// Mitsubishi GX Works2 project: L02_EIP_LIBRARY   PLC: FX3G

// task Task_01 (event TRUE, interval 0, priority 31): POU_01
// user libraries (not included): BIT_TO_INT

PROGRAM POU_01
VAR
  FB_EIP_MASTER_1 : FB_EIP_MASTER;
END_VAR
(* structured ladder/FBD written out as ST: instructions are called as NAME(EN, inputs, outputs); _pN, _eN, _tN stand for wires *)
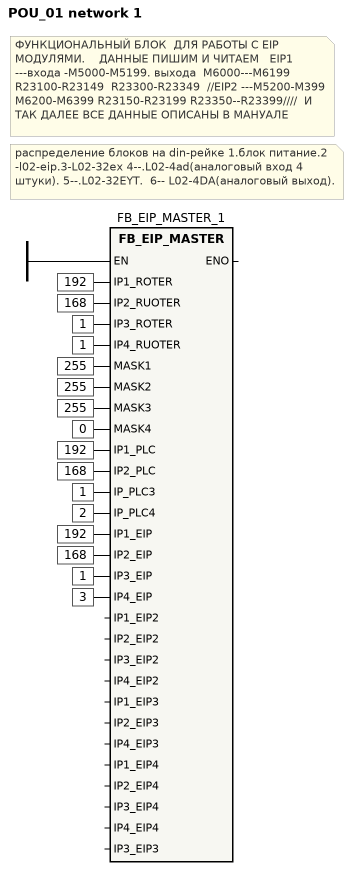
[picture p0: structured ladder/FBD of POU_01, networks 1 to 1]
(* network 1 *)
(* ФУНКЦИОНАЛЬНЫЙ БЛОК  ДЛЯ РАБОТЫ С EIP МОДУЛЯМИ.    ДАННЫЕ ПИШИМ И ЧИТАЕМ   EIP1 ---входа -М5000-М5199. выхода  M6000---M6199  R23100-R23149  R23300-R23349  //EIP2 ---M5200-M399  M6200-M6399 R23150-R23199 R23350--R23399////  И ТАК ДАЛЕЕ ВСЕ ДАННЫЕ ОПИСАНЫ В МАНУАЛЕ *)
(* распределение блоков на din-рейке 1.блок питание.2 -l02-eip.3-L02-32ex 4--.L02-4ad(аналоговый вход 4 штуки). 5--.L02-32EYT.  6-- L02-4DA(аналоговый выход). *)
FB_EIP_MASTER_1(EN := TRUE, IP1_ROTER := 192, IP2_RUOTER := 168, IP3_ROTER := 1, IP4_RUOTER := 1, MASK1 := 255, MASK2 := 255, MASK3 := 255, MASK4 := 0, IP1_PLC := 192, IP2_PLC := 168, IP_PLC3 := 1, IP_PLC4 := 2, IP1_EIP := 192, IP2_EIP := 168, IP3_EIP := 1, IP4_EIP := 3);
END_PROGRAM

FUNCTION_BLOCK FB_EIP_MASTER
VAR_INPUT
  IP1_ROTER : INT;
  IP2_RUOTER : INT;
  IP3_ROTER : INT;
  IP4_RUOTER : INT;
  MASK1 : INT;
  MASK2 : INT;
  MASK3 : INT;
  MASK4 : INT;
  IP1_PLC : INT;
  IP2_PLC : INT;
  IP_PLC3 : INT;
  IP_PLC4 : INT;
  IP1_EIP : INT;
  IP2_EIP : INT;
  IP3_EIP : INT;
  IP4_EIP : INT;
  IP1_EIP2 : INT;
  IP2_EIP2 : INT;
  IP3_EIP2 : INT;
  IP4_EIP2 : INT;
  IP1_EIP3 : INT;
  IP2_EIP3 : INT;
  IP4_EIP3 : INT;
  IP1_EIP4 : INT;
  IP2_EIP4 : INT;
  IP3_EIP4 : INT;
  IP4_EIP4 : INT;
  IP3_EIP3 : INT;
END_VAR
(* structured ladder/FBD written out as ST: instructions are called as NAME(EN, inputs, outputs); _pN, _eN, _tN stand for wires *)
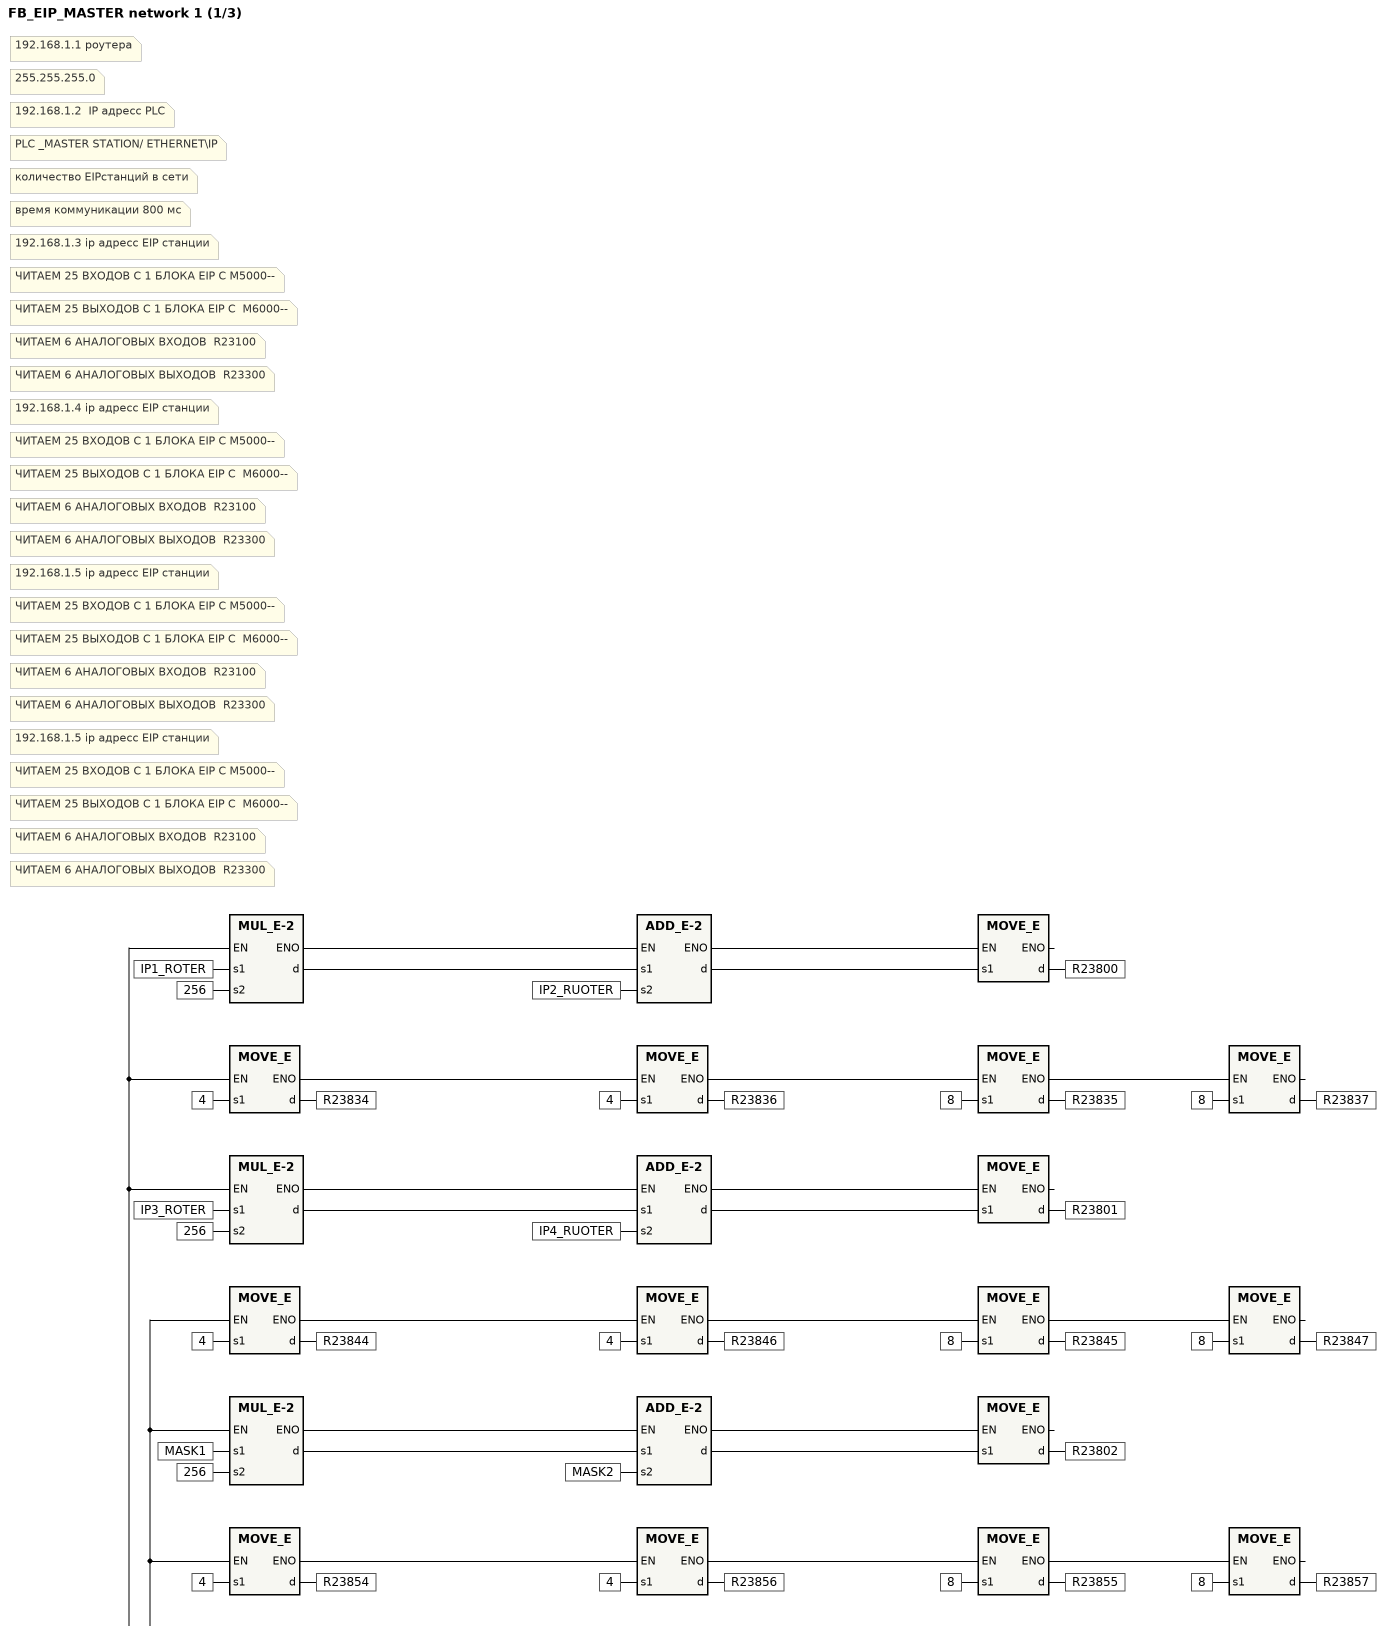
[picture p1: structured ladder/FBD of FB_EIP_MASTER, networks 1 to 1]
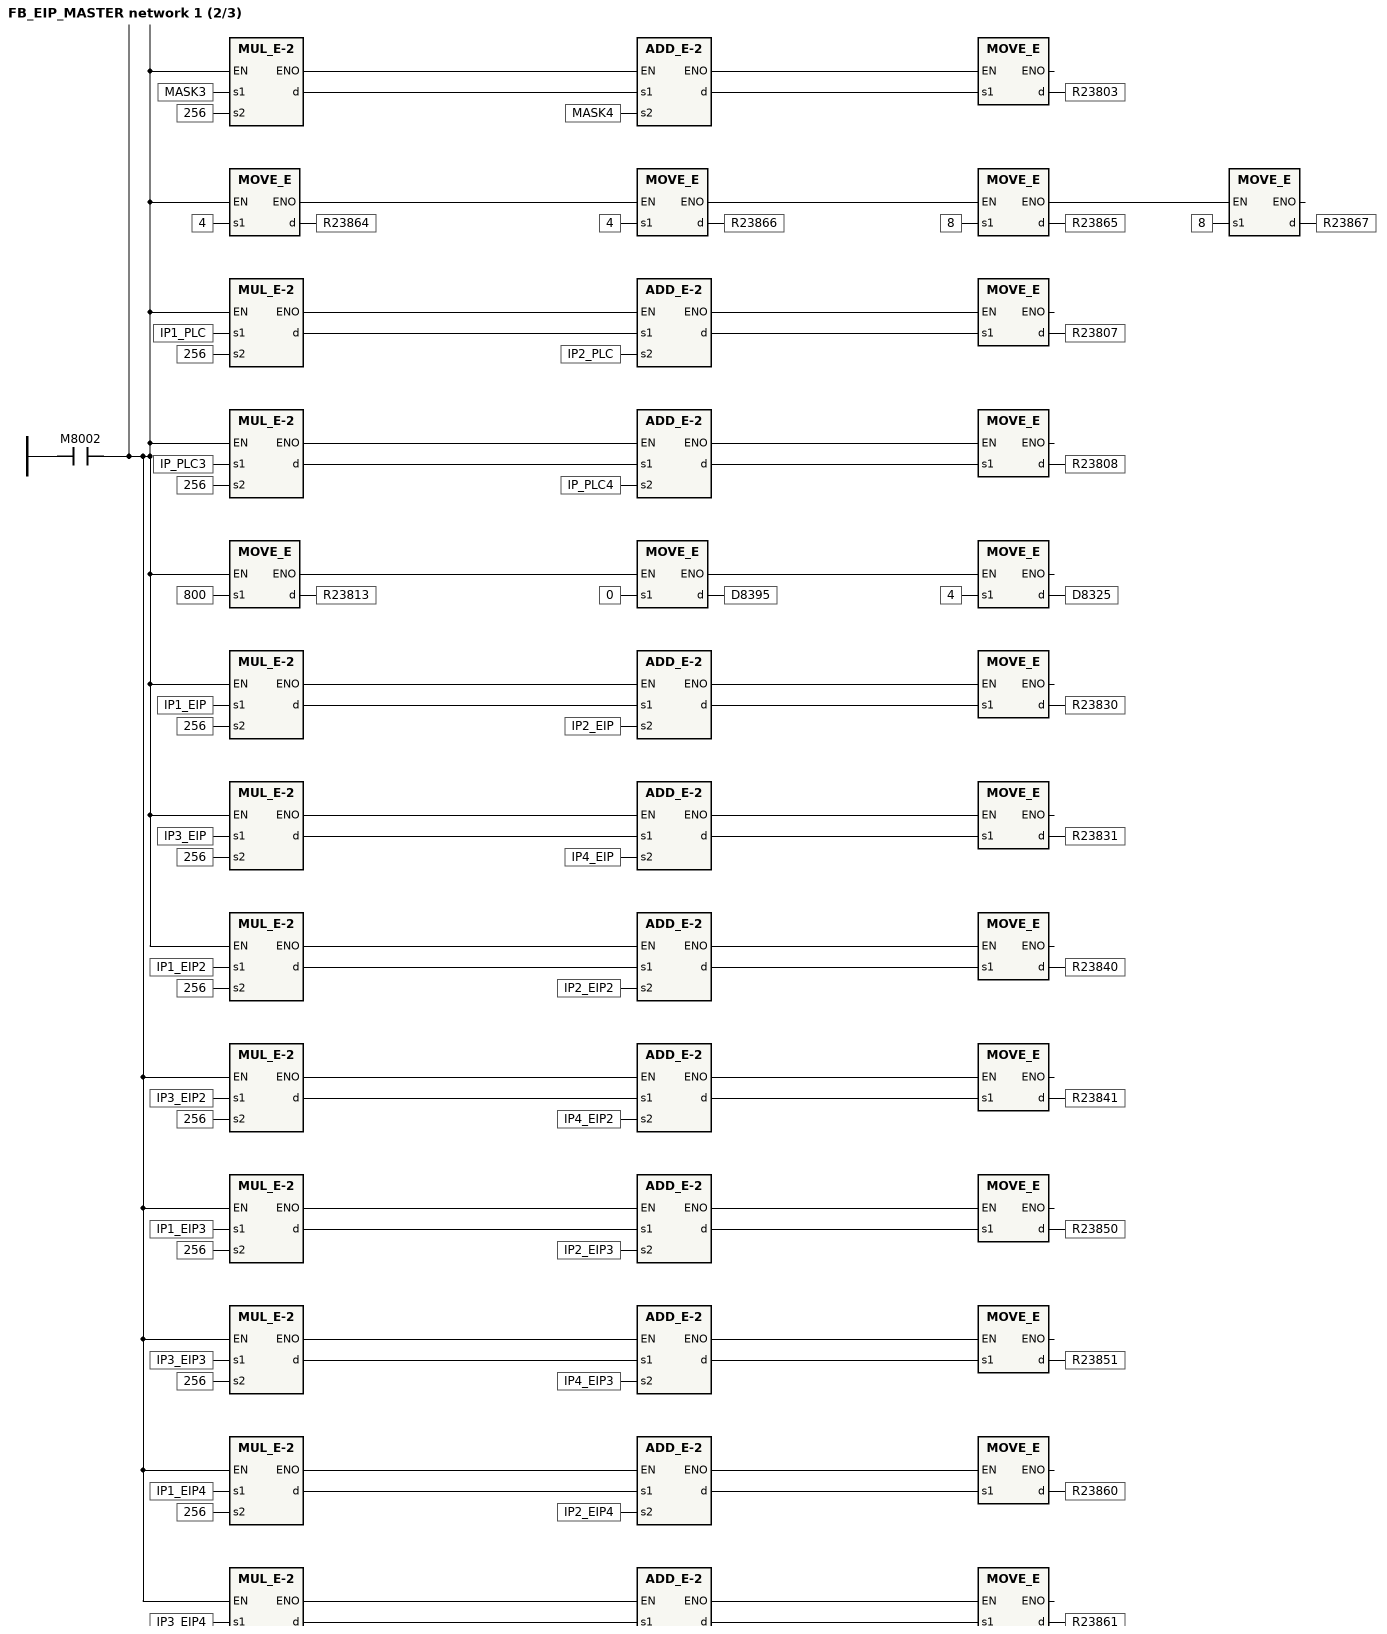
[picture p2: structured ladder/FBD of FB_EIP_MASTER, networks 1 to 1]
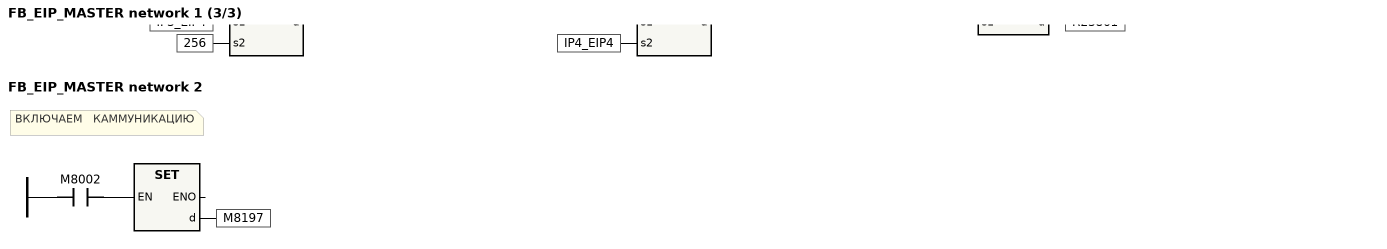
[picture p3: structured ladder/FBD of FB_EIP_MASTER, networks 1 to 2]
(* network 1 *)
(* 192.168.1.1 роутера *)
(* 255.255.255.0 *)
(* 192.168.1.2  IP адресс PLC *)
(* PLC _MASTER STATION/ ETHERNET\IP *)
(* количество EIPстанций в сети *)
(* время коммуникации 800 мс *)
(* 192.168.1.3 ip адресс EIP станции *)
(* ЧИТАЕМ 25 ВХОДОВ С 1 БЛОКА EIP C M5000-- *)
(* ЧИТАЕМ 25 ВЫХОДОВ С 1 БЛОКА EIP C  M6000-- *)
(* ЧИТАЕМ 6 АНАЛОГОВЫХ ВХОДОВ  R23100 *)
(* ЧИТАЕМ 6 АНАЛОГОВЫХ ВЫХОДОВ  R23300 *)
(* 192.168.1.4 ip адресс EIP станции *)
(* ЧИТАЕМ 25 ВХОДОВ С 1 БЛОКА EIP C M5000-- *)
(* ЧИТАЕМ 25 ВЫХОДОВ С 1 БЛОКА EIP C  M6000-- *)
(* ЧИТАЕМ 6 АНАЛОГОВЫХ ВХОДОВ  R23100 *)
(* ЧИТАЕМ 6 АНАЛОГОВЫХ ВЫХОДОВ  R23300 *)
(* 192.168.1.5 ip адресс EIP станции *)
(* ЧИТАЕМ 25 ВХОДОВ С 1 БЛОКА EIP C M5000-- *)
(* ЧИТАЕМ 25 ВЫХОДОВ С 1 БЛОКА EIP C  M6000-- *)
(* ЧИТАЕМ 6 АНАЛОГОВЫХ ВХОДОВ  R23100 *)
(* ЧИТАЕМ 6 АНАЛОГОВЫХ ВЫХОДОВ  R23300 *)
(* 192.168.1.5 ip адресс EIP станции *)
(* ЧИТАЕМ 25 ВХОДОВ С 1 БЛОКА EIP C M5000-- *)
(* ЧИТАЕМ 25 ВЫХОДОВ С 1 БЛОКА EIP C  M6000-- *)
(* ЧИТАЕМ 6 АНАЛОГОВЫХ ВХОДОВ  R23100 *)
(* ЧИТАЕМ 6 АНАЛОГОВЫХ ВЫХОДОВ  R23300 *)
_e2 := MUL_E(M8002, IP1_ROTER, 256, _t1);
_e4 := ADD_E(_e2, _t1, IP2_RUOTER, _t3);
MOVE_E(_e4, _t3, R23800);
_e6 := MUL_E(M8002, IP3_ROTER, 256, _t5);
_e8 := ADD_E(_e6, _t5, IP4_RUOTER, _t7);
MOVE_E(_e8, _t7, R23801);
_e10 := MUL_E(M8002, MASK1, 256, _t9);
_e12 := ADD_E(_e10, _t9, MASK2, _t11);
MOVE_E(_e12, _t11, R23802);
_e14 := MUL_E(M8002, MASK3, 256, _t13);
_e16 := ADD_E(_e14, _t13, MASK4, _t15);
MOVE_E(_e16, _t15, R23803);
_e18 := MUL_E(M8002, IP1_PLC, 256, _t17);
_e20 := ADD_E(_e18, _t17, IP2_PLC, _t19);
MOVE_E(_e20, _t19, R23807);
_e22 := MUL_E(M8002, IP_PLC3, 256, _t21);
_e24 := ADD_E(_e22, _t21, IP_PLC4, _t23);
MOVE_E(_e24, _t23, R23808);
_e25 := MOVE_E(M8002, 800, R23813);
_e26 := MOVE_E(_e25, 0, D8395);
MOVE_E(_e26, 4, D8325);
_e28 := MUL_E(M8002, IP1_EIP, 256, _t27);
_e30 := ADD_E(_e28, _t27, IP2_EIP, _t29);
MOVE_E(_e30, _t29, R23830);
_e32 := MUL_E(M8002, IP3_EIP, 256, _t31);
_e34 := ADD_E(_e32, _t31, IP4_EIP, _t33);
MOVE_E(_e34, _t33, R23831);
_e35 := MOVE_E(M8002, 4, R23834);
_e36 := MOVE_E(_e35, 4, R23836);
_e37 := MOVE_E(_e36, 8, R23835);
MOVE_E(_e37, 8, R23837);
_e39 := MUL_E(M8002, IP1_EIP2, 256, _t38);
_e41 := ADD_E(_e39, _t38, IP2_EIP2, _t40);
MOVE_E(_e41, _t40, R23840);
_e43 := MUL_E(M8002, IP3_EIP2, 256, _t42);
_e45 := ADD_E(_e43, _t42, IP4_EIP2, _t44);
MOVE_E(_e45, _t44, R23841);
_e46 := MOVE_E(M8002, 4, R23844);
_e47 := MOVE_E(_e46, 4, R23846);
_e48 := MOVE_E(_e47, 8, R23845);
MOVE_E(_e48, 8, R23847);
_e50 := MUL_E(M8002, IP1_EIP3, 256, _t49);
_e52 := ADD_E(_e50, _t49, IP2_EIP3, _t51);
MOVE_E(_e52, _t51, R23850);
_e54 := MUL_E(M8002, IP3_EIP3, 256, _t53);
_e56 := ADD_E(_e54, _t53, IP4_EIP3, _t55);
MOVE_E(_e56, _t55, R23851);
_e57 := MOVE_E(M8002, 4, R23854);
_e58 := MOVE_E(_e57, 4, R23856);
_e59 := MOVE_E(_e58, 8, R23855);
MOVE_E(_e59, 8, R23857);
_e61 := MUL_E(M8002, IP1_EIP4, 256, _t60);
_e63 := ADD_E(_e61, _t60, IP2_EIP4, _t62);
MOVE_E(_e63, _t62, R23860);
_e65 := MUL_E(M8002, IP3_EIP4, 256, _t64);
_e67 := ADD_E(_e65, _t64, IP4_EIP4, _t66);
MOVE_E(_e67, _t66, R23861);
_e68 := MOVE_E(M8002, 4, R23864);
_e69 := MOVE_E(_e68, 4, R23866);
_e70 := MOVE_E(_e69, 8, R23865);
MOVE_E(_e70, 8, R23867);
(* network 2 *)
(* ВКЛЮЧАЕМ   КАММУНИКАЦИЮ *)
SET(M8002, M8197);
END_FUNCTION_BLOCK
